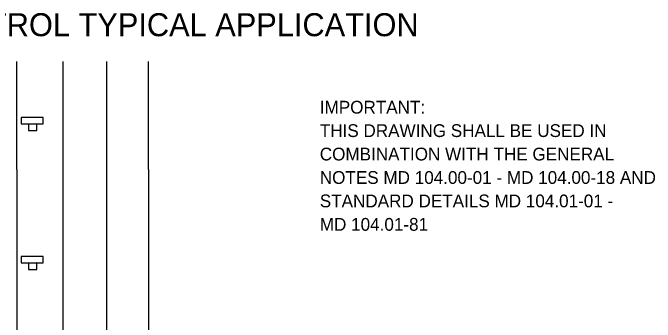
# Model space of a CAD drawing. Extents: x 1531.4 to 1538.6, y 1528.5 to 1539.8.
# Drawn here: x 1534.713 to 1537.729, y 1538.385 to 1539.837 of the extents above; entities that cross this region are included whole.
import ezdxf

# ---------------------------------------------------------------- set-up
doc = ezdxf.new("R2010")
doc.units = 0
for name, color, linetype in [('DETL-LINE', 7, 'Continuous'), ('DETL-NOTE', 7, 'Continuous'), ('DETL-TITL', 7, 'Continuous'), ('USER-BORD', 7, 'Continuous')]:
    doc.layers.add(name, color=color, linetype=linetype)

# ---------------------------------------------------------------- blocks, each defined once
blk = doc.blocks.new('SIGN')
at = {"layer": 'USER-BORD'}
for points in [[(-0.0013, 0.0018), (0.0011, 0.0019), (0.0011, 0.0037), (-0.0013, 0.0037)], [(-0.0031, 0.0018), (-0.0031, 0), (0.0032, 0), (0.0032, 0.0018)]]:
    blk.add_lwpolyline(points, close=True, dxfattribs=at)

msp = doc.modelspace()

# ---------------------------------------------------------------- linework, layer by layer
at = {"layer": 'DETL-LINE'}
for p, q in [((1534.7308, 1539.1023), (1534.7308, 1539.6093)), ((1534.948, 1539.6093), (1534.948, 1539.1023)), ((1535.153, 1539.6093), (1535.153, 1536.9908)), ((1535.3502, 1539.1023), (1535.3502, 1539.6093)), ((1534.7308, 1539.1023), (1534.7308, 1537.6532)), ((1534.948, 1539.1023), (1534.948, 1536.5764)), ((1535.3502, 1539.1023), (1535.3502, 1536.5764))]:
    msp.add_line(p, q, dxfattribs=at)
for points in [[(1535.153, 1539.6093), (1535.153, 1539.4905)], [(1535.153, 1538.778), (1535.153, 1538.6593)], [(1535.153, 1538.6593), (1535.153, 1538.5405)]]:
    msp.add_lwpolyline(points, dxfattribs=at)

# ---------------------------------------------------------------- block references
at = {"layer": 'DETL-LINE', "xscale": 16.482020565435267, "yscale": 16.482020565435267, "rotation": 180}
for p in [(1534.8039, 1539.3458), (1534.8039, 1538.6931)]:
    msp.add_blockref('SIGN', p, dxfattribs=at)

# ---------------------------------------------------------------- texts
at = {"layer": 'DETL-NOTE'}
for s, p in [('IMPORTANT:', (1536.154, 1539.3644)), ('THIS DRAWING SHALL BE USED IN', (1536.154, 1539.2544)), ('COMBINATION WITH THE GENERAL', (1536.154, 1539.1444)), ('NOTES MD 104.00-01 - MD 104.00-18 AND', (1536.154, 1539.0344)), ('STANDARD DETAILS MD 104.01-01 -', (1536.154, 1538.9244)), ('MD 104.01-81', (1536.154, 1538.8144))]:
    msp.add_text(s, height=0.06, dxfattribs=at).set_placement(p)
at = {"layer": 'DETL-TITL'}
msp.add_text('TEMPORARY TRAFFIC CONTROL TYPICAL APPLICATION', height=0.108, dxfattribs=at).set_placement((1532.6702, 1539.7278))

doc.saveas('drawing.dxf')
